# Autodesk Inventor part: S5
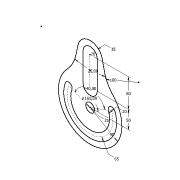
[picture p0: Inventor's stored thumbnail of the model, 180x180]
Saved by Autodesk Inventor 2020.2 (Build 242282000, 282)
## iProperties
Created: 2013-12
Part Number: S5
Material: Ogólny
Document SubType Name: Modeling
Designer: F.Stasiak
Density: 1 g/cm^3
Appearance: Domyślna
Manager: www.cadconsulting.pl
Company: Fabian Stasiak CAD Consulting
Author: F.Stasiak
Subject: Zbiór ćwiczeń. Autodesk Inventor 2020. Kurs podstawowy
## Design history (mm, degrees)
sketch "Szkic1"
  geometry: L1 (0, 50)-(0, 130); L2 (-20, 50)-(-20, 130); L3 (20, 130)-(20, 50); L4 (-34.17, 137.575)-(-40.56, 108.754); L5 (34.17, 137.575)-(40.56, 108.754); L6 (0, 0)-(-61.08, 22.231); L7 (0, 0)-(65, 0); L8 (0, 0)-(61.08, 22.231); C1 r 12.5 at (0, 0); A1 r 20 centre (0, 50) between (-20, 50) and (20, 50); A2 r 20 centre (0, 130) between (20, 130) and (-20, 130); A3 r 100 centre (-138.189, 130.398) between (-65.458, 61.768) and (-40.56, 108.754); A4 r 100 centre (138.189, 130.398) between (40.56, 108.754) and (65.458, 61.768); A5 r 90 centre (0, 0) between (-65.458, 61.768) and (65.458, 61.768); A6 r 35 centre (0, 130) between (34.17, 137.575) and (-34.17, 137.575); A7 r 65 centre (0, 0) between (-61.08, 22.231) and (61.08, 22.231); A8 r 75 centre (0, 0) between (-70.477, 25.652) and (70.477, 25.652); A9 r 55 centre (0, 0) between (-51.683, 18.811) and (51.683, 18.811); A10 r 10 centre (-61.08, 22.231) between (-51.683, 18.811) and (-70.477, 25.652); A11 r 10 centre (61.08, 22.231) between (70.477, 25.652) and (51.683, 18.811); 2 further points
  constraints: 24 point on circle, 18 end point, 12 centre point, 11 tangent, 4 coincident, 4 symmetric about line, 1 equal length, 1 horizontal, 1 midpoint, 1 parallel, 1 point on line, 1 vertical, 1 other
  dimensions: "d1" = 20 radius of A2; "d3" = 35 radius of A6; "d4" = 80 distance of L1.start L1.end; "d5" = 50 distance of L1.start point (0, 0); "d6" = 90 radius of A5; "d7" = 100 radius of A4; "d8" = 25 deg angle of L5 L4; "d9" = 65 radius of A7; "d10" = 160 deg angle of L7 L6; "d11" = 140 deg angle of L8 L6; "d12" = 20 diameter of A11; "d13" = 25 diameter of C1
